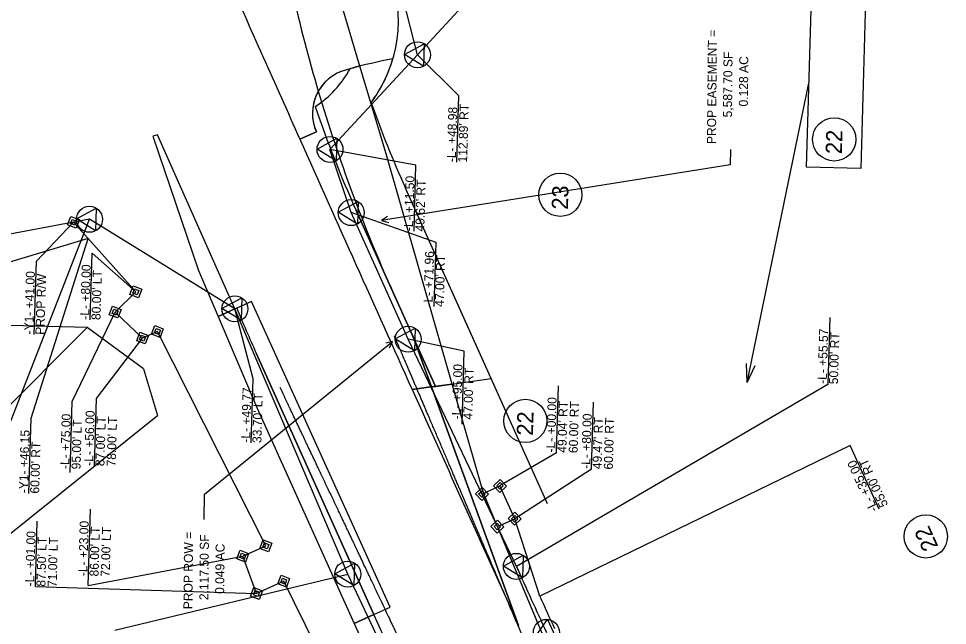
# Model space of a CAD drawing. Extents: x 2097272 to 2098144, y 685104 to 689282.
# Drawn here: x 2097622 to 2098136, y 685590 to 685927 of the extents above; entities that cross this region are included whole.
import ezdxf

# ---------------------------------------------------------------- set-up
doc = ezdxf.new("R2010")
doc.units = 0
for name, color, linetype in [('Default', 7, 'Continuous'), ('Prop Easement Construction', 7, 'Continuous'), ('Prop Easement Construction Station Offsets', 7, 'Continuous'), ('Prop Easement Permanent Drainage', 7, 'Continuous'), ('Prop Easement Permanent Drainage Station Offsets', 7, 'Continuous'), ('Prop Easement Permanent Utility', 7, 'Continuous'), ('Prop Easement Permanent Utility Station Offsets', 7, 'Continuous'), ('Prop Parcel Number CELL', 7, 'Continuous'), ('Prop ROW Marker CELL', 7, 'Continuous'), ('Prop ROW Permanent Easement CELL', 7, 'Continuous'), ('Prop ROW RW Lines', 7, 'Continuous'), ('Prop ROW Station Offsets', 7, 'Continuous'), ('Scratch_Level_1', 7, 'Continuous'), ('Scratch_Level_3', 7, 'Continuous'), ('Scratch_Level_5', 7, 'Continuous'), ('Scratch_Level_6', 7, 'Continuous')]:
    doc.layers.add(name, color=color, linetype=linetype)

msp = doc.modelspace()

# ---------------------------------------------------------------- linework, layer by layer
at = {"layer": 'Default'}
msp.add_lwpolyline([(2097778.56, 685621.21), (2097778.56, 685621.21)], close=True, dxfattribs=at)
at = {"layer": 'Prop Easement Construction'}
for p, q in [((2097660.04, 685804.9), (2097587.39, 685783.15)), ((2097910.45, 685606.71), (2097896.59, 685649.57))]:
    msp.add_line(p, q, dxfattribs=at)
msp.add_arc((2102411.4, 687654.74), 4945, 204.4666, 204.69579, dxfattribs=at)
at = {"layer": 'Prop Easement Construction Station Offsets'}
for p, q in [((2097628.5, 685705.3), (2097660.04, 685804.9)), ((2097627.29, 685663.64), (2097628.5, 685705.3)), ((2098082.56, 685690.12), (2097910.45, 685606.71)), ((2098098.55, 685654.97), (2098082.56, 685690.12))]:
    msp.add_line(p, q, dxfattribs=at)
at = {"layer": 'Prop Easement Permanent Drainage'}
for p, q in [((2097878.39, 685663.31), (2097888.38, 685667.81)), ((2097896.59, 685649.57), (2097888.38, 685667.81)), ((2097886.99, 685645.25), (2097896.59, 685649.57))]:
    msp.add_line(p, q, dxfattribs=at)
at = {"layer": 'Prop Easement Permanent Drainage Station Offsets'}
for p, q in [((2097919.74, 685686.12), (2097920.82, 685723.27)), ((2097939.21, 685677.02), (2097940.29, 685714.16)), ((2097919.74, 685686.12), (2097888.38, 685667.81)), ((2097939.21, 685677.02), (2097896.59, 685649.57))]:
    msp.add_line(p, q, dxfattribs=at)
at = {"layer": 'Prop Easement Permanent Utility'}
for p, q in [((2097842.65, 685906.79), (2097920.79, 685991.37)), ((2097686.52, 685775.33), (2097651.97, 685813.91)), ((2097675.06, 685764.15), (2097686.52, 685775.33)), ((2097690.31, 685749.73), (2097675.06, 685764.15)), ((2097698.52, 685753.43), (2097690.31, 685749.73)), ((2097758.57, 685634.61), (2097698.52, 685753.43)), ((2097745.81, 685628.86), (2097758.57, 685634.61)), ((2097753.47, 685608.19), (2097745.81, 685628.86)), ((2097768.52, 685614.96), (2097753.47, 685608.19)), ((2097799.72, 685551.87), (2097768.52, 685614.96))]:
    msp.add_line(p, q, dxfattribs=at)
at = {"layer": 'Prop Easement Permanent Utility Station Offsets'}
for p, q in [((2097631.42, 685792.42), (2097651.97, 685813.91)), ((2097661.31, 685759.83), (2097662.38, 685796.76)), ((2097662.38, 685796.76), (2097686.52, 685775.33)), ((2097630.24, 685751.64), (2097631.42, 685792.42)), ((2097651.32, 685714.62), (2097675.06, 685764.15)), ((2097650.18, 685675.26), (2097651.32, 685714.62)), ((2097663.61, 685678.85), (2097664.7, 685716.25)), ((2097660.17, 685612.67), (2097661.4, 685654.95)), ((2097630.89, 685612.02), (2097631.94, 685648.28)), ((2097660.17, 685612.67), (2097745.81, 685628.86)), ((2097630.89, 685612.02), (2097753.47, 685608.19))]:
    msp.add_line(p, q, dxfattribs=at)
msp.add_lwpolyline([(2097664.7, 685716.25), (2097690.31, 685749.73)], dxfattribs=at)
at = {"layer": 'Prop Parcel Number CELL'}
for q in [(2098059.76, 685891.94), (2098025.06, 685735.62), (2098029.86, 685734.63)]:
    msp.add_line((2098025.42, 685725.19), q, dxfattribs=at)
msp.add_lwpolyline([(2098058.38, 685844.55), (2098061.29, 685944.51), (2098091.27, 685943.64), (2098088.37, 685843.68)], close=True, dxfattribs=at)
for centre in [(2098073.72, 685859.89), (2097921.88, 685829.17), (2097902.48, 685703.8), (2098124.46, 685639.82)]:
    msp.add_circle(centre, 12, dxfattribs=at)
at = {"layer": 'Prop ROW Marker CELL'}
for p, q in [((2097842.65, 685906.79), (2097842.65, 685906.79)), ((2097794.18, 685854.31), (2097794.18, 685854.31)), ((2097660.87, 685815.58), (2097660.87, 685815.58)), ((2097805.96, 685819.28), (2097805.96, 685819.28)), ((2097741.47, 685765.93), (2097741.47, 685765.93)), ((2097837.54, 685749.1), (2097837.54, 685749.1)), ((2097888.38, 685667.81), (2097888.38, 685667.81)), ((2097878.39, 685663.31), (2097878.39, 685663.31)), ((2097886.99, 685645.25), (2097886.99, 685645.25)), ((2097896.59, 685649.57), (2097896.59, 685649.57)), ((2097897.5, 685623.19), (2097897.5, 685623.19)), ((2097804.03, 685618.88), (2097804.03, 685618.88))]:
    msp.add_line(p, q, dxfattribs=at)
for points in [[(2097846.07, 685900.44), (2097835.46, 685907), (2097846.43, 685912.93)], [(2097797.59, 685847.96), (2097786.98, 685854.52), (2097797.96, 685860.46)], [(2097809.37, 685812.93), (2097798.76, 685819.49), (2097809.74, 685825.42)], [(2097664.28, 685809.23), (2097653.67, 685815.79), (2097664.65, 685821.72)], [(2097744.89, 685759.58), (2097734.28, 685766.14), (2097745.25, 685772.07)], [(2097840.96, 685742.75), (2097830.34, 685749.31), (2097841.32, 685755.25)], [(2097807.45, 685612.53), (2097796.84, 685619.09), (2097807.81, 685625.02)], [(2097900.92, 685616.84), (2097890.3, 685623.4), (2097901.28, 685629.33)], [(2097920, 685582.43), (2097907.58, 685583.65), (2097914.82, 685593.81)]]:
    msp.add_lwpolyline(points, close=True, dxfattribs=at)
for centre in [(2097842.65, 685906.79), (2097794.18, 685854.31), (2097805.96, 685819.28), (2097660.87, 685815.58), (2097741.47, 685765.93), (2097837.54, 685749.1), (2097897.5, 685623.19), (2097804.03, 685618.88), (2097914.13, 685586.63)]:
    msp.add_circle(centre, 7.2, dxfattribs=at)
at = {"layer": 'Prop ROW Permanent Easement CELL'}
for p, q in [((2097651.97, 685813.91), (2097651.97, 685813.91)), ((2097686.52, 685775.33), (2097686.52, 685775.33)), ((2097675.06, 685764.15), (2097675.06, 685764.15)), ((2097698.52, 685753.43), (2097698.52, 685753.43)), ((2097690.31, 685749.73), (2097690.31, 685749.73)), ((2097758.57, 685634.61), (2097758.57, 685634.61)), ((2097745.81, 685628.86), (2097745.81, 685628.86)), ((2097768.52, 685614.96), (2097768.52, 685614.96)), ((2097753.47, 685608.19), (2097753.47, 685608.19))]:
    msp.add_line(p, q, dxfattribs=at)
for points in [[(2097648.7, 685812.42), (2097650.48, 685817.19), (2097655.25, 685815.4), (2097653.46, 685810.63)], [(2097650.33, 685813.16), (2097651.23, 685815.55), (2097653.61, 685814.65), (2097652.72, 685812.27)], [(2097683.24, 685773.84), (2097685.03, 685778.61), (2097689.8, 685776.83), (2097688.01, 685772.06)], [(2097684.88, 685774.59), (2097685.78, 685776.97), (2097688.16, 685776.08), (2097687.27, 685773.7)], [(2097671.78, 685762.66), (2097673.57, 685767.43), (2097678.33, 685765.64), (2097676.55, 685760.87)], [(2097673.42, 685763.4), (2097674.31, 685765.79), (2097676.7, 685764.89), (2097675.8, 685762.51)], [(2097695.24, 685751.94), (2097697.03, 685756.71), (2097701.79, 685754.92), (2097700.01, 685750.15)], [(2097696.88, 685752.68), (2097697.77, 685755.07), (2097700.16, 685754.17), (2097699.26, 685751.79)], [(2097687.03, 685748.24), (2097688.82, 685753.01), (2097693.59, 685751.23), (2097691.8, 685746.46)], [(2097688.67, 685748.99), (2097689.57, 685751.37), (2097691.95, 685750.48), (2097691.06, 685748.1)], [(2097884.79, 685667.91), (2097888.49, 685671.41), (2097891.98, 685667.71), (2097888.28, 685664.21)], [(2097874.8, 685663.42), (2097878.5, 685666.91), (2097881.99, 685663.21), (2097878.29, 685659.71)], [(2097886.59, 685667.86), (2097888.44, 685669.61), (2097890.18, 685667.76), (2097888.33, 685666.01)], [(2097876.6, 685663.37), (2097878.45, 685665.11), (2097880.19, 685663.26), (2097878.34, 685661.51)], [(2097893, 685649.68), (2097896.7, 685653.17), (2097900.19, 685649.47), (2097896.49, 685645.97)], [(2097894.79, 685649.62), (2097896.65, 685651.37), (2097898.39, 685649.52), (2097896.54, 685647.77)], [(2097883.4, 685645.36), (2097887.1, 685648.85), (2097890.59, 685645.15), (2097886.89, 685641.65)], [(2097885.2, 685645.3), (2097887.05, 685647.05), (2097888.79, 685645.2), (2097886.94, 685643.45)], [(2097755.3, 685633.12), (2097757.08, 685637.89), (2097761.85, 685636.1), (2097760.07, 685631.33)], [(2097756.94, 685633.86), (2097757.83, 685636.25), (2097760.21, 685635.35), (2097759.32, 685632.97)], [(2097742.53, 685627.37), (2097744.32, 685632.14), (2097749.08, 685630.35), (2097747.3, 685625.59)], [(2097744.17, 685628.12), (2097745.06, 685630.5), (2097747.45, 685629.61), (2097746.55, 685627.22)], [(2097765.24, 685613.47), (2097767.03, 685618.23), (2097771.79, 685616.45), (2097770.01, 685611.68)], [(2097766.88, 685614.21), (2097767.77, 685616.6), (2097770.15, 685615.7), (2097769.26, 685613.32)], [(2097750.19, 685606.69), (2097751.98, 685611.46), (2097756.75, 685609.68), (2097754.96, 685604.91)], [(2097751.83, 685607.44), (2097752.72, 685609.82), (2097755.11, 685608.93), (2097754.22, 685606.55)]]:
    msp.add_lwpolyline(points, close=True, dxfattribs=at)
at = {"layer": 'Prop ROW RW Lines'}
for p, q in [((2097842.65, 685906.79), (2097830.26, 685955.58)), ((2097794.18, 685854.31), (2097842.65, 685906.79)), ((2097805.96, 685819.28), (2097794.18, 685854.31)), ((2097660.87, 685815.58), (2097585.74, 685801.45)), ((2097741.47, 685765.93), (2097660.87, 685815.58)), ((2097837.54, 685749.1), (2097805.96, 685819.28)), ((2097804.03, 685618.88), (2097741.47, 685765.93)), ((2097897.5, 685623.19), (2097837.54, 685749.1)), ((2097931.37, 685351.45), (2097804.03, 685618.88))]:
    msp.add_line(p, q, dxfattribs=at)
for end in [204.29472, 204.69579]:
    msp.add_arc((2102411.4, 687654.74), 4950, 204.23092, end, dxfattribs=at)
at = {"layer": 'Prop ROW Station Offsets'}
for p, q in [((2097865.61, 685884.09), (2097842.65, 685906.79)), ((2097864.54, 685847.16), (2097865.61, 685884.09)), ((2097841.85, 685845.67), (2097794.18, 685854.31)), ((2097840.79, 685808.94), (2097841.85, 685845.67)), ((2097616.18, 685700.94), (2097660.87, 685815.58)), ((2097852.98, 685802.81), (2097805.96, 685819.28)), ((2097851.94, 685767.18), (2097852.98, 685802.81)), ((2097751.51, 685727.07), (2097741.47, 685765.93)), ((2098071.2, 685761.22), (2098070.12, 685724.09)), ((2097868.61, 685742.42), (2097837.54, 685749.1)), ((2097867.44, 685702), (2097868.61, 685742.42)), ((2097750.48, 685691.67), (2097751.51, 685727.07)), ((2098070.12, 685724.09), (2097897.5, 685623.19)), ((2097674.97, 685587.86), (2097804.03, 685618.88))]:
    msp.add_line(p, q, dxfattribs=at)
at = {"layer": 'Scratch_Level_1'}
msp.add_line((2097821.52, 685606.22), (2097821.52, 685606.22), dxfattribs=at)
for points, degree in [([(2097855.19, 685691.61), (2097846.77, 685711.32), (2097838.36, 685731.03), (2097829.85, 685750.96)], 2), ([(2097794, 685664.33), (2097784.83, 685683.69), (2097775.65, 685703.06), (2097766.48, 685722.43)], 2), ([(2097880.43, 685632.47), (2097872.02, 685652.18), (2097863.6, 685671.9), (2097855.19, 685691.61)], 2), ([(2097821.52, 685606.22), (2097812.35, 685625.59), (2097803.18, 685644.96), (2097794, 685664.33)], 2), ([(2097905.75, 685573.76), (2097905.68, 685573.91), (2097905.58, 685574.14), (2097905.48, 685574.37), (2097905.41, 685574.52), (2097905.38, 685574.6), (2097905.28, 685574.83), (2097905.21, 685574.98), (2097905.13, 685575.17), (2097905.11, 685575.21), (2097905.09, 685575.27), (2097905.08, 685575.29), (2097905.06, 685575.32), (2097905.06, 685575.33), (2097905.05, 685575.35), (2097905.05, 685575.35), (2097905.01, 685575.44), (2097904.98, 685575.52), (2097904.68, 685576.2), (2097904.41, 685576.81), (2097903.61, 685578.64), (2097903.08, 685579.86), (2097901.48, 685583.52), (2097898.29, 685590.84), (2097895.12, 685598.16), (2097891.97, 685605.5), (2097890.92, 685607.94), (2097889.34, 685611.61), (2097888.82, 685612.83), (2097888.17, 685614.36), (2097888.03, 685614.67), (2097887.84, 685615.13), (2097887.77, 685615.28), (2097887.69, 685615.47), (2097887.67, 685615.53), (2097887.64, 685615.6), (2097887.63, 685615.63), (2097887.62, 685615.64), (2097887.61, 685615.65), (2097887.59, 685615.7), (2097887.58, 685615.74), (2097887.55, 685615.8), (2097887.54, 685615.82), (2097887.53, 685615.85), (2097887.52, 685615.87), (2097887.52, 685615.88), (2097887.45, 685616.04), (2097887.38, 685616.2), (2097887.25, 685616.5), (2097887.19, 685616.66), (2097886.99, 685617.11), (2097886.86, 685617.42), (2097884.63, 685622.64), (2097882.53, 685627.56), (2097880.43, 685632.47)], 3), ([(2097849.36, 685547.99), (2097849.22, 685548.29), (2097849.07, 685548.59), (2097848.85, 685549.04), (2097848.76, 685549.23), (2097848.67, 685549.42), (2097848.63, 685549.5), (2097848.61, 685549.54), (2097848.56, 685549.65), (2097848.23, 685550.33), (2097847.31, 685552.22), (2097845.26, 685556.46), (2097841.17, 685564.94), (2097836.51, 685574.64), (2097832.46, 685583.14), (2097830.59, 685587.09), (2097829.79, 685588.76), (2097829.54, 685589.3), (2097829.41, 685589.56), (2097829.36, 685589.68), (2097829.32, 685589.75), (2097829.31, 685589.79), (2097829.14, 685590.13), (2097829, 685590.44), (2097828.71, 685591.04), (2097828.57, 685591.35), (2097826.12, 685596.51), (2097823.82, 685601.36), (2097821.52, 685606.22)], 3)]:
    msp.add_open_spline(points, degree=degree, dxfattribs=at)
at = {"layer": 'Scratch_Level_3'}
for p, q in [((2097786.64, 685864), (2097777.52, 685859.91)), ((2097777.52, 685859.91), (2097786.64, 685864)), ((2097750.63, 685770.08), (2097742.46, 685766.38)), ((2097827.53, 685600.58), (2097750.63, 685770.08)), ((2097850.38, 685722.69), (2097840.28, 685750.34)), ((2097753.29, 685741.37), (2097818.49, 685596.51)), ((2097850.06, 685722.64), (2097839.73, 685721.22)), ((2097839.73, 685721.22), (2097850.06, 685722.64)), ((2097850.38, 685722.69), (2097850.06, 685722.64)), ((2097850.06, 685722.64), (2097850.38, 685722.69)), ((2097898.71, 685590.46), (2097850.38, 685722.69)), ((2097818.49, 685596.51), (2097827.53, 685600.58))]:
    msp.add_line(p, q, dxfattribs=at)
for points in [[(2097840.28, 685750.34), (2097838.22, 685754.9), (2097828.98, 685775.44)], [(2097818.49, 685596.51), (2097818.49, 685596.51)]]:
    msp.add_lwpolyline(points, dxfattribs=at)
for centre, radius, start, end in [((2162207.31, 714677.79), 70580.94, 204.016055, 204.097808), ((2098631.45, 686136.6), 880, 192.79074, 196.50581), ((2097809.45, 685874.23), 25, 150.3965, 204.1563), ((2097809.45, 685874.23), 25, 150.3965, 204.1563), ((2098631.45, 686136.6), 880, 196.50581, 204.23092), ((2162207.31, 714677.79), 70580.94, 204.097808, 204.221202), ((2098631.45, 686136.6), 963, 202.60949, 204.23092), ((2162207.31, 714677.79), 70580.94, 204.221202, 204.3376459)]:
    msp.add_arc(centre, radius, start, end, dxfattribs=at)
at = {"layer": 'Scratch_Level_5'}
for p, q in [((2097786.64, 685864), (2097777.52, 685859.91)), ((2098016.13, 685854.26), (2098016.05, 685845.72)), ((2098016.05, 685845.72), (2097822.79, 685814.92)), ((2097914.83, 685657.78), (2097836.05, 685832.83)), ((2097883.56, 685727.25), (2097836.05, 685832.83)), ((2097852.58, 685722.99), (2097808.69, 685820.51)), ((2097808.69, 685820.51), (2097852.58, 685722.99)), ((2097826.05, 685817.12), (2097822.79, 685814.92)), ((2097822.79, 685814.92), (2097826.58, 685813.84)), ((2097724.53, 685663.19), (2097828.9, 685747.91)), ((2097828.9, 685747.91), (2097825.09, 685746.91)), ((2097827.2, 685744.35), (2097828.9, 685747.91)), ((2097839.73, 685721.22), (2097850.06, 685722.64)), ((2097850.06, 685722.64), (2097852.58, 685722.99)), ((2097852.58, 685722.99), (2097883.56, 685727.25)), ((2097724.4, 685649.16), (2097724.53, 685663.19))]:
    msp.add_line(p, q, dxfattribs=at)
for centre, radius, start, end in [((2097754.89, 685926.19), 77.25, 323.4807, 20.6008), ((2097884.86, 685609.77), 300, 100.7231, 105.3821), ((2097754.89, 685926.19), 77.25, 323.4807, 343.7185), ((2097809.45, 685874.23), 25, 105.3976, 204.1563), ((2097754.89, 685926.19), 57.25, 302.8427, 331.673), ((2097754.89, 685926.19), 57.25, 302.8427, 331.673), ((2097884.86, 685609.77), 300, 105.3821, 105.8721), ((2098415.1, 686093.44), 665, 198.89464, 204.23092), ((2098415.1, 686093.44), 665, 198.89464, 204.23092), ((2098415.1, 686093.44), 635, 199.61974, 204.23092), ((2098415.1, 686093.44), 635, 199.61974, 204.23092), ((2162207.31, 714677.79), 70580.94, 204.097808, 204.221202)]:
    msp.add_arc(centre, radius, start, end, dxfattribs=at)
at = {"layer": 'Scratch_Level_6'}
for p, q in [((2097810.75, 685900.48), (2097796.42, 685948.5)), ((2097825.28, 685851.79), (2097810.75, 685900.48)), ((2097698.58, 685862.44), (2097696.01, 685861.69)), ((2097696.01, 685861.69), (2097721.2, 685787.22)), ((2097741.47, 685765.93), (2097698.58, 685862.44)), ((2097861.88, 685724.27), (2097825.28, 685851.79)), ((2097721.2, 685787.22), (2097732.13, 685761.65)), ((2097741.47, 685765.93), (2097732.13, 685761.65)), ((2097732.13, 685761.65), (2097741.47, 685765.93)), ((2097742.46, 685766.38), (2097741.47, 685765.93)), ((2097732.13, 685761.65), (2097753.65, 685711.35)), ((2097492.76, 685588.34), (2097659.48, 685755.67)), ((2097659.48, 685755.67), (2097607.95, 685756.95)), ((2097690.88, 685732.71), (2097659.48, 685755.67)), ((2097840.28, 685750.34), (2097850.38, 685722.69)), ((2097818.43, 685596.49), (2097753.29, 685741.37)), ((2097690.88, 685732.71), (2097698.62, 685706.84)), ((2097850.38, 685722.69), (2097861.88, 685724.27)), ((2097861.88, 685724.27), (2097850.38, 685722.69)), ((2097850.38, 685722.69), (2097898.71, 685590.46)), ((2097879.27, 685663.71), (2097861.88, 685724.27)), ((2097556.81, 685593.22), (2097698.62, 685706.84)), ((2097753.65, 685711.35), (2097807.67, 685591.54)), ((2097914.75, 685579.02), (2097879.27, 685663.71)), ((2097818.43, 685596.49), (2097807.67, 685591.54)), ((2097807.67, 685591.54), (2097818.43, 685596.49)), ((2097870.23, 685483.9), (2097818.43, 685596.49)), ((2097807.67, 685591.54), (2097825.72, 685551.52))]:
    msp.add_line(p, q, dxfattribs=at)
msp.add_lwpolyline([(2097828.98, 685775.44), (2097838.22, 685754.9), (2097840.28, 685750.34)], dxfattribs=at)
for centre, radius, start, end in [((2098631.45, 686136.6), 880, 192.79074, 196.50581), ((2097809.45, 685874.23), 25, 105.3976, 150.3965), ((2097809.45, 685874.23), 25, 105.3976, 150.3965), ((2097884.86, 685609.77), 300, 104.3018, 105.8721), ((2097884.86, 685609.77), 300, 104.3018, 105.8721), ((2098631.45, 686136.6), 880, 196.50581, 204.23092), ((2098631.45, 686136.6), 963, 202.60949, 204.23092)]:
    msp.add_arc(centre, radius, start, end, dxfattribs=at)

# ---------------------------------------------------------------- texts
at = {"layer": 'Prop Easement Construction Station Offsets'}
for s, rotation, p in [('-Y1- +46.15', 88.3348, (2097626.66, 685663.66)), ("60.00' RT", 88.3348, (2097632.91, 685663.48)), ('-L- +35.00', 114.4674, (2098097.99, 685654.71)), ("55.00' RT", 114.4674, (2098103.67, 685657.3))]:
    msp.add_text(s, height=5, rotation=rotation, dxfattribs=at).set_placement(p)
at = {"layer": 'Prop Easement Permanent Drainage Station Offsets'}
for s, p in [('-L- +00.00', (2097918.96, 685686.28)), ("49.04' RT", (2097925.21, 685686.1)), ("60.00' RT", (2097931.46, 685685.92)), ('-L- +80.00', (2097938.44, 685677.18)), ("49.47' RT", (2097944.69, 685677)), ("60.00' RT", (2097950.93, 685676.81))]:
    msp.add_text(s, height=5, rotation=88.3348, dxfattribs=at).set_placement(p)
at = {"layer": 'Prop Easement Permanent Utility Station Offsets'}
for s, p in [('-L- +80.00', (2097660.68, 685759.85)), ('-Y1- +41.00', (2097629.61, 685751.66)), ('PROP R/W', (2097635.86, 685751.48)), ("80.00' LT", (2097666.93, 685759.67)), ('-L- +75.00', (2097649.61, 685677.09)), ('-L- +56.00', (2097662.86, 685678.88)), ("95.00' LT", (2097655.86, 685676.91)), ("87.00' LT", (2097669.11, 685678.69)), ("78.00' LT", (2097675.36, 685678.51)), ('-L- +23.00', (2097659.57, 685617.72)), ("86.00' LT", (2097665.82, 685617.53)), ("72.00' LT", (2097672.06, 685617.35)), ('-L- +01.00', (2097630.14, 685612.04)), ("87.50' LT", (2097636.38, 685611.86)), ("71.00' LT", (2097642.63, 685611.68))]:
    msp.add_text(s, height=5, rotation=88.3348, dxfattribs=at).set_placement(p)
at = {"layer": 'Prop Parcel Number CELL'}
for s, rotation, p in [('22', 88.3348, (2098077.9, 685851.62)), ('23', 88.3348, (2097926.07, 685820.83)), ('22', 88.3348, (2097906.67, 685695.53)), ('22', 114.4674, (2098131.56, 685634.21))]:
    msp.add_text(s, height=9, rotation=rotation, dxfattribs=at).set_placement(p)
at = {"layer": 'Prop ROW Station Offsets'}
for s, p in [('-L- +48.98', (2097863.91, 685847.18)), ("112.89' RT", (2097870.16, 685847)), ('-L- +11.50', (2097840.16, 685808.96)), ("49.62' RT", (2097846.41, 685808.78)), ('-L- +71.96', (2097850.99, 685767.21)), ("47.00' RT", (2097857.24, 685767.03)), ('-L- +55.57', (2098069.5, 685724.27)), ("50.00' RT", (2098075.75, 685724.09)), ('-L- +95.00', (2097866.77, 685704.64)), ("47.00' RT", (2097873.02, 685704.46)), ('-L- +49.77', (2097749.86, 685691.69)), ("33.70' LT", (2097756.11, 685691.51))]:
    msp.add_text(s, height=5, rotation=88.3348, dxfattribs=at).set_placement(p)
at = {"layer": 'Scratch_Level_5'}
for s, p in [('PROP EASEMENT =', (2098008.13, 685857.26)), ('5,587.70 SF', (2098017.02, 685872.04)), ('0.128 AC', (2098025.83, 685878.1)), ('PROP ROW =', (2097717.94, 685599.42)), ('2,117.50 SF', (2097726.74, 685604.47)), ('0.049 AC', (2097735.52, 685607.9))]:
    msp.add_text(s, height=5, rotation=89.4699, dxfattribs=at).set_placement(p)

doc.saveas('drawing.dxf')
